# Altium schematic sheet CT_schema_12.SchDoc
size 281 x 153 mm
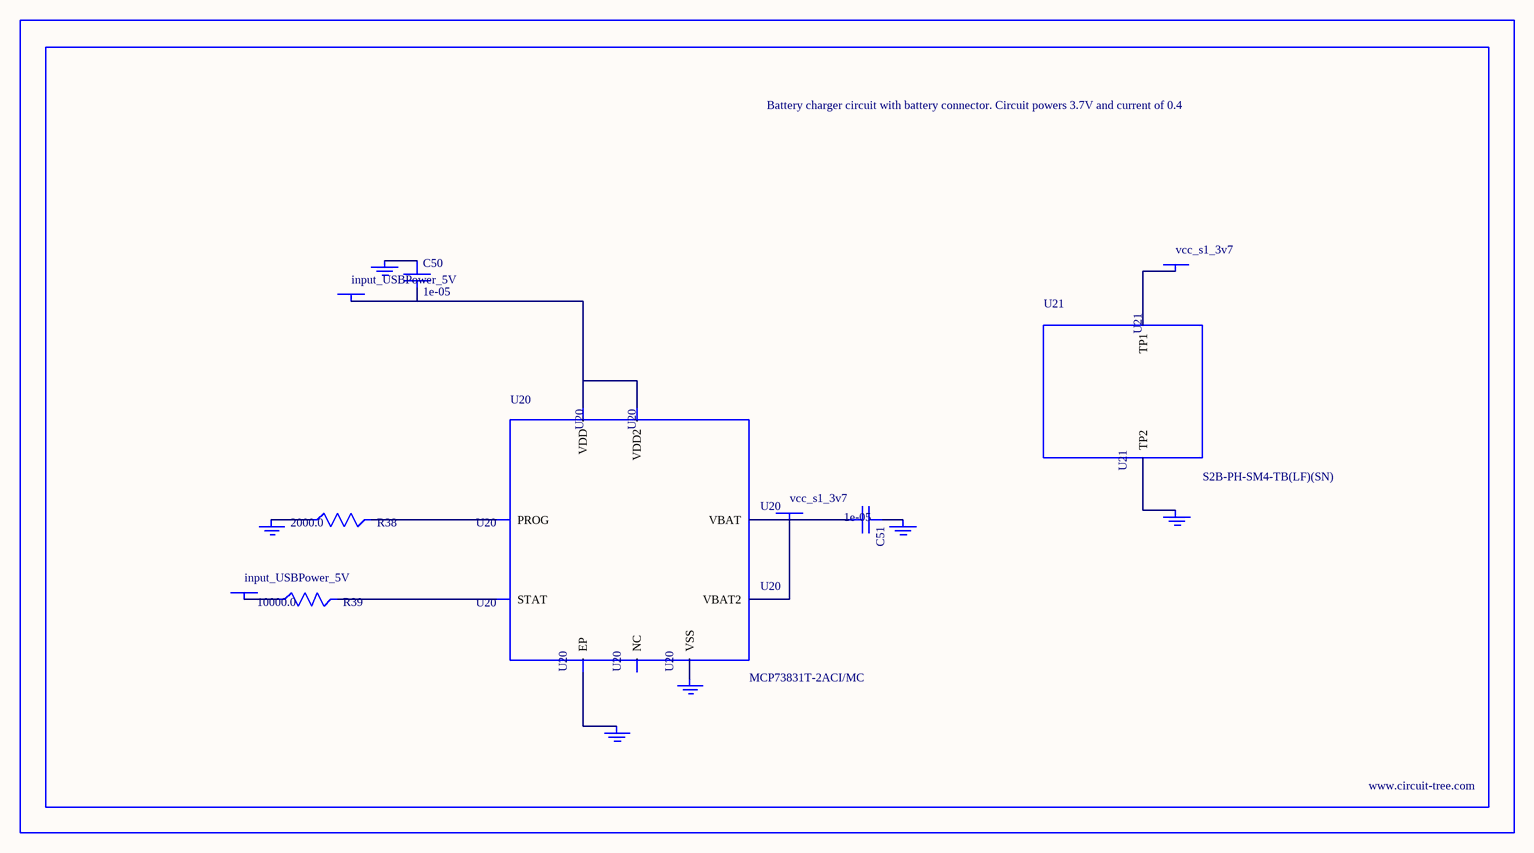
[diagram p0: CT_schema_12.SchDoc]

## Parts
BORDER11  (no value)
C50  1e-05  [C1206]
C51  1e-05  [C1206]
GND_INSTANCE_11_0  (no value)
GND_INSTANCE_11_1  (no value)
GND_INSTANCE_11_2  (no value)
GND_INSTANCE_11_3  (no value)
GND_INSTANCE_11_4  (no value)
GND_INSTANCE_11_5  (no value)
POWER_INSTANCE_11_0  input_USBPower_5V
POWER_INSTANCE_11_1  input_USBPower_5V
POWER_INSTANCE_11_2  vcc_s1_3v7
POWER_INSTANCE_11_3  vcc_s1_3v7
R38  2000.0  [R0603]
R39  10000.0  [R0603]
U20  MCP73831T-2ACI/MC  [DFN8_2X3MC]
U21  S2B-PH-SM4-TB(LF)(SN)  [JST-2-SMD]

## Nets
NetC50_1: C50.1 GND_INSTANCE_11_0.0(GND)
NetC50_2: C50.2 POWER_INSTANCE_11_0.0(PWR) U20.1(VDD) U20.2(VDD2)
NetC51_1: C51.1 GND_INSTANCE_11_1.0(GND)
NetC51_2: C51.2 POWER_INSTANCE_11_2.0(PWR) U20.3(VBAT) U20.4(VBAT2)
NetGND_INSTANCE_11_2_0: GND_INSTANCE_11_2.0(GND) R38.1
NetGND_INSTANCE_11_3_0: GND_INSTANCE_11_3.0(GND) U20.9(EP)
NetGND_INSTANCE_11_4_0: GND_INSTANCE_11_4.0(GND) U20.6(VSS)
NetGND_INSTANCE_11_5_0: GND_INSTANCE_11_5.0(GND) U21.2(TP2)
NetPOWER_INSTANCE_11_1_0: POWER_INSTANCE_11_1.0(PWR) R39.1
NetPOWER_INSTANCE_11_3_0: POWER_INSTANCE_11_3.0(PWR) U21.1(TP1)
NetR38_2: R38.2 U20.8(PROG)
NetR39_2: R39.2 U20.5(STAT)

Not connected (* = marked no-connect by the designer): U20 7(NC)

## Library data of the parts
BORDER11 = BORDER_PAGE11
C50 C51 = C1206C106K3RACTU
GND_INSTANCE_11_0-GND_INSTANCE_11_5 = GND
POWER_INSTANCE_11_0-POWER_INSTANCE_11_3 = PWR
R38 = RC0603JR-072KL
R39 = RC0603JR-0710KL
